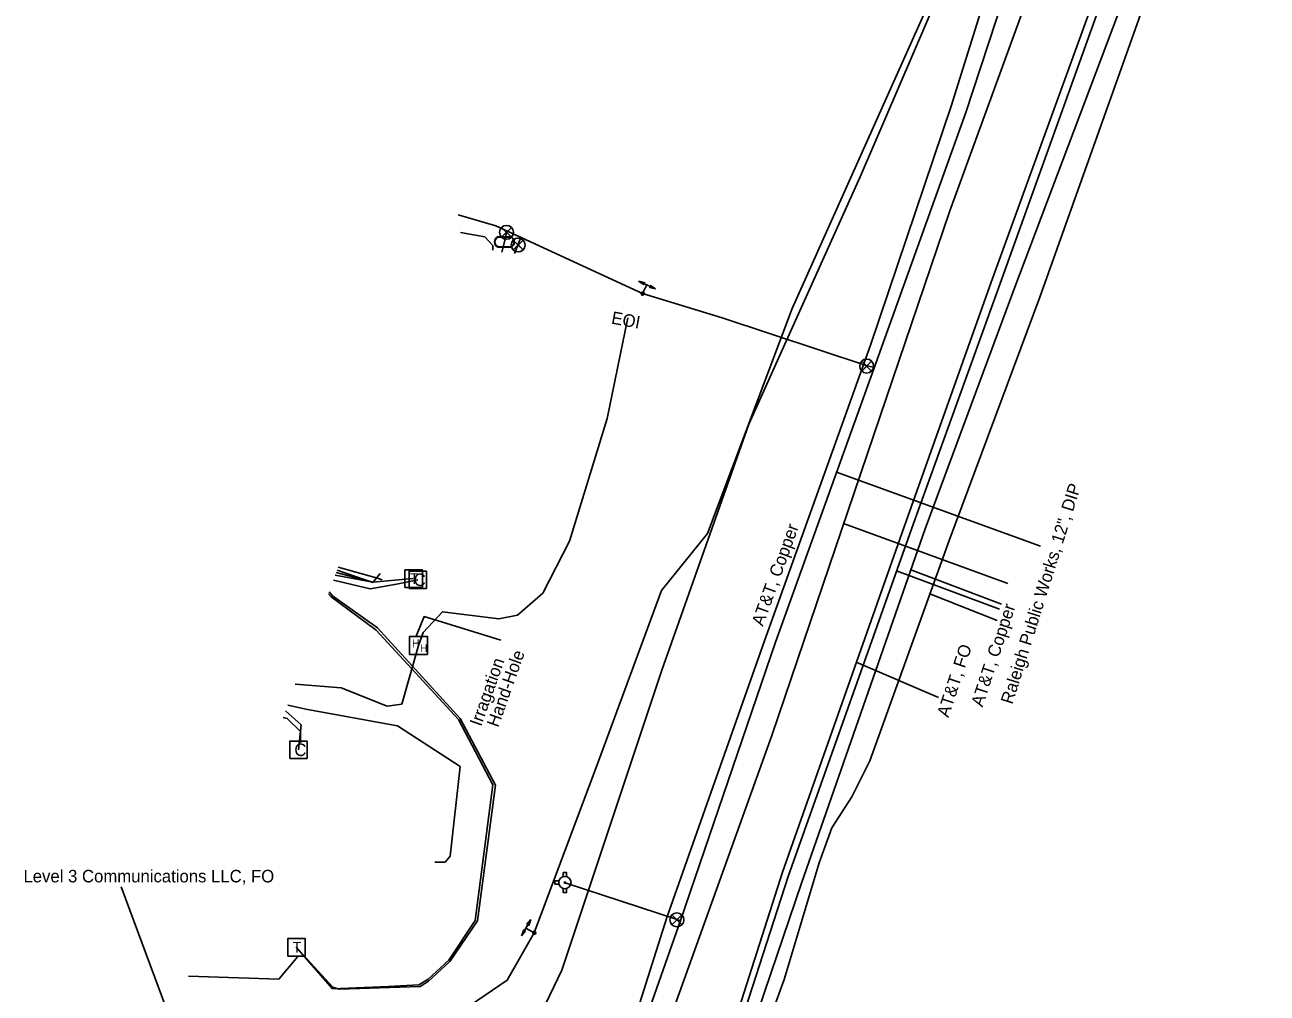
# Model space of a CAD drawing. Extents: x 2070721 to 2083340, y 729290 to 737883.
# Drawn here: x 2080815 to 2081212.7, y 732995.1 to 733305.1 of the extents above; entities that cross this region are included whole.
import ezdxf

# ---------------------------------------------------------------- set-up
doc = ezdxf.new("R2010")
doc.units = 0
for name, color, linetype in [('Exist Utilities Gas UG Line SUE LOS B', 7, 'Continuous'), ('Exist Utilities Power Hand Hole CELL', 7, 'Continuous'), ('Exist Utilities Power Hand Hole Leader', 7, 'Continuous'), ('Exist Utilities Power Hand Hole Text', 7, 'Continuous'), ('Exist Utilities Power UG Cable SUE LOS B', 7, 'Continuous'), ('Exist Utilities Telephone Change of Service SUE CELL', 7, 'Continuous'), ('Exist Utilities Telephone Pedestal CELL', 7, 'Continuous'), ('Exist Utilities Telephone UG Cable SUE LOS C', 7, 'Continuous'), ('Exist Utilities Telephone UG Cable SUE LOS C Leader', 7, 'Continuous'), ('Exist Utilities Telephone UG Cable SUE LOS C Text', 7, 'Continuous'), ('Exist Utilities Telephone UG FO SUE LOS B', 7, 'Continuous'), ('Exist Utilities Telephone UG FO SUE LOS B Leader', 7, 'Continuous'), ('Exist Utilities Telephone UG FO SUE LOS B Text', 7, 'Continuous'), ('Exist Utilities Telephone UG FO SUE LOS C', 7, 'Continuous'), ('Exist Utilities Telephone UG FO SUE LOS C Leader', 7, 'Continuous'), ('Exist Utilities Telephone UG FO SUE LOS C Text', 7, 'Continuous'), ('Exist Utilities TV Pedestal CELL', 7, 'Continuous'), ('Exist Utilities TV UG Cable SUE LOS C', 7, 'Continuous'), ('Exist Utilities Water Change of Service SUE CELL', 7, 'Continuous'), ('Exist Utilities Water Fire Hydrant CELL', 7, 'Continuous'), ('Exist Utilities Water Meter CELL', 7, 'Continuous'), ('Exist Utilities Water UG Line SUE LOS B', 7, 'Continuous'), ('Exist Utilities Water UG Line SUE LOS B Leader', 7, 'Continuous'), ('Exist Utilities Water UG Line SUE LOS B Text', 7, 'Continuous'), ('Exist Utilities Water UG Line SUE LOS C', 7, 'Continuous'), ('Exist Utilities Water Valve CELL', 7, 'Continuous')]:
    doc.layers.add(name, color=color, linetype=linetype)

msp = doc.modelspace()

# ---------------------------------------------------------------- linework, layer by layer
at = {"layer": 'Exist Utilities Gas UG Line SUE LOS B'}
msp.add_lwpolyline([(2080924.17, 732884.04), (2080930.33, 732882.17), (2080949.02, 732923.62), (2080986.84, 733002.49), (2081018.88, 733098.52), (2081046.79, 733177.28), (2081082.41, 733256.43), (2081124.09, 733353.56), (2081157.6, 733423.49)], dxfattribs=at)
at = {"layer": 'Exist Utilities Power Hand Hole CELL'}
msp.add_line((2080941.08, 733106.31), (2080941.08, 733106.31), dxfattribs=at)
msp.add_lwpolyline([(2080938.13, 733103.58), (2080943.88, 733103.58), (2080943.88, 733109.33), (2080938.13, 733109.33), (2080938.13, 733103.58)], dxfattribs=at)
at = {"layer": 'Exist Utilities Power Hand Hole Leader'}
msp.add_lwpolyline([(2080940.24, 733109.35), (2080942.86, 733115.65), (2080967.41, 733108.17)], dxfattribs=at)
at = {"layer": 'Exist Utilities Power UG Cable SUE LOS B'}
for points in [[(2080964.78, 733232.99), (2080964.78, 733234.42), (2080962.25, 733237.2), (2080954.44, 733238.62)], [(2080935.69, 733087.68), (2080940.98, 733106.38), (2080942.52, 733110.53), (2080948.63, 733117.2), (2080966.72, 733114.92), (2080972.71, 733116.12), (2080980.82, 733123.17), (2080989.3, 733139.79), (2081001.41, 733179.09), (2081008, 733211.34)], [(2080929.38, 733127.43), (2080927.91, 733127.95), (2080915.26, 733131.44)], [(2080914.92, 733130.51), (2080926.37, 733126.62), (2080928.73, 733129.47)], [(2080935.69, 733087.68), (2080930.93, 733087), (2080916.25, 733092.82), (2080901.57, 733094)], [(2080899.12, 733087.29), (2080905.51, 733085.89), (2080934.27, 733080.68), (2080954.39, 733067.67), (2080951.13, 733038.98), (2080949.52, 733037.11), (2080946.26, 733037.11)], [(2080897.68, 733083.35), (2080898.97, 733083.08), (2080903.24, 733078.92), (2080903.24, 733075.29)], [(2080867.39, 733000.52), (2080896.29, 732999.64), (2080902.38, 733006.86)]]:
    msp.add_lwpolyline(points, dxfattribs=at)
at = {"layer": 'Exist Utilities Telephone Change of Service SUE CELL'}
for p, q in [((2080976.94, 733018.69), (2080973.99, 733013.51)), ((2080975.39, 733015.97), (2080976.94, 733018.69)), ((2080978.07, 733014.44), (2080975.39, 733015.97)), ((2080978.07, 733014.44), (2080978.07, 733014.44))]:
    msp.add_line(p, q, dxfattribs=at)
for points in [[(2080976.94, 733018.69), (2080976.27, 733016.81), (2080976.18, 733017.35), (2080975.72, 733017.17)], [(2080973.99, 733013.51), (2080974.67, 733015.4), (2080974.76, 733014.86), (2080975.21, 733015.04)]]:
    msp.add_lwpolyline(points, close=True, dxfattribs=at)
msp.add_circle((2080978.07, 733014.44), 0.517, dxfattribs=at)
at = {"layer": 'Exist Utilities Telephone Pedestal CELL'}
for p, q in [((2080939.36, 733127.86), (2080939.36, 733127.86)), ((2080901.87, 733009.84), (2080901.87, 733009.84))]:
    msp.add_line(p, q, dxfattribs=at)
for points in [[(2080936.63, 733125.03), (2080942.23, 733125.03), (2080942.23, 733130.63), (2080936.63, 733130.63), (2080936.63, 733125.03)], [(2080899.15, 733007.01), (2080904.74, 733007.01), (2080904.74, 733012.61), (2080899.15, 733012.61), (2080899.15, 733007.01)]]:
    msp.add_lwpolyline(points, dxfattribs=at)
at = {"layer": 'Exist Utilities Telephone UG Cable SUE LOS C'}
for points in [[(2080953.21, 732796.69), (2081054.09, 733077.62), (2081111.09, 733245.57), (2081176.08, 733423.78), (2081231.97, 733580.28), (2081320.16, 733847.08), (2081418.84, 734093.09), (2081467.34, 734224.03), (2081494.06, 734287.2), (2081526.74, 734352.01), (2081556, 734404.62), (2081808.13, 734757.73), (2081845.73, 734804.26), (2081874.67, 734821.58), (2081898.66, 734810.94), (2081917.15, 734795.51)], [(2080971.45, 732791.05), (2081028.93, 732955.93), (2081037.58, 732965.12), (2081059.34, 733032.5), (2081099.5, 733145.5), (2081127.24, 733222.27), (2081165.53, 733329.08), (2081197.08, 733415.76), (2081225.51, 733493.81), (2081252.34, 733568.18), (2081252.65, 733568.73)], [(2080977.85, 732787.5), (2081009.55, 732879.6), (2081045.87, 732978.13), (2081063.56, 733030.35), (2081103.18, 733143.81), (2081131.57, 733220.23), (2081172.06, 733327.38), (2081203.1, 733413.05), (2081232.13, 733491.49), (2081257.07, 733565.11), (2081257.51, 733566.68)], [(2080980.31, 732787.04), (2081017.13, 732880.26), (2081044.65, 732962.53), (2081058.02, 732999.54), (2081069.26, 733036.84), (2081073.31, 733048.09), (2081079.75, 733057.99), (2081085.51, 733069.49), (2081110.84, 733140.06), (2081139.9, 733217.95), (2081177.19, 733322.59), (2081208.97, 733410.75), (2081237.5, 733489.4), (2081264.77, 733561.01)], [(2080944.31, 732798.44), (2080951.65, 732814.71), (2080971.81, 732874.01), (2081001.7, 732960.05), (2081020.52, 733019.4), (2081051.78, 733107.87), (2081085.75, 733202.6), (2081111.57, 733279.04), (2081128.94, 733334.77), (2081148.26, 733379.04), (2081175.1, 733448.52), (2081180.53, 733478.86)], [(2080939.29, 733127.87), (2080926.33, 733126.73), (2080914.34, 733128.93)], [(2080944.24, 732998.92), (2080950.99, 733005.26), (2080959.87, 733018.3), (2080965.67, 733061.66), (2080954.33, 733083.1), (2080927.85, 733112.11), (2080913.43, 733122.3), (2080912.38, 733123.56)], [(2080944.24, 732998.92), (2080941.57, 732997.28), (2080915.55, 732996.45), (2080913.58, 732997), (2080901.87, 733009.83)]]:
    msp.add_lwpolyline(points, dxfattribs=at)
at = {"layer": 'Exist Utilities Telephone UG Cable SUE LOS C Leader'}
for p, q in [((2081077.1, 733145.5), (2081129.64, 733126.3)), ((2081094.04, 733130.35), (2081127.01, 733118.02)), ((2081098.66, 733130.6), (2081127.65, 733119.69)), ((2081104.65, 733122.9), (2081126.24, 733114.42))]:
    msp.add_line(p, q, dxfattribs=at)
at = {"layer": 'Exist Utilities Telephone UG FO SUE LOS B'}
for points in [[(2081060.57, 733214.24), (2081129.62, 733368.62), (2081142.99, 733409.6), (2081173.13, 733492.79), (2081185.02, 733525.68), (2081211.4, 733608.97), (2081237.57, 733665.91), (2081235.81, 733672.2)], [(2080974.54, 732788.58), (2081004.48, 732877.32), (2081038.77, 732975.1), (2081057.5, 733033.86), (2081097.09, 733146.25), (2081124.3, 733222.73), (2081163.35, 733330.31), (2081194.31, 733416.96), (2081222.79, 733494.92), (2081247.13, 733564.12), (2081248.81, 733567.64)], [(2080978.07, 733014.44), (2080998.67, 733069.39), (2081018.84, 733124), (2081033.47, 733142.22), (2081060.57, 733214.24)], [(2080939.29, 733127.87), (2080926.33, 733126.73), (2080914.65, 733129.77)], [(2080944.08, 732999.62), (2080950.66, 733005.65), (2080959.18, 733018.4), (2080964.82, 733061.81), (2080953.78, 733082.77), (2080927.47, 733111.31), (2080913.03, 733121.96), (2080912.17, 733123)], [(2080944.08, 732999.62), (2080941.08, 732997.75), (2080931.36, 732997.26), (2080913.5, 732996.51), (2080901.87, 733009.84)]]:
    msp.add_lwpolyline(points, dxfattribs=at)
at = {"layer": 'Exist Utilities Telephone UG FO SUE LOS B Leader'}
msp.add_line((2081081.16, 733101.05), (2081107.43, 733089.72), dxfattribs=at)
at = {"layer": 'Exist Utilities Telephone UG FO SUE LOS C'}
msp.add_lwpolyline([(2080858.37, 732979.69), (2080864.15, 732979.69), (2080906.18, 732979.56), (2080947.92, 732984.72), (2080969.41, 732999.27), (2080978.07, 733014.44)], dxfattribs=at)
at = {"layer": 'Exist Utilities Telephone UG FO SUE LOS C Leader'}
msp.add_line((2080864.15, 732979.69), (2080845.85, 733029.15), dxfattribs=at)
at = {"layer": 'Exist Utilities TV Pedestal CELL'}
for p, q in [((2080940.76, 733127.44), (2080940.76, 733127.44)), ((2080902.54, 733073.03), (2080902.54, 733073.03))]:
    msp.add_line(p, q, dxfattribs=at)
for points in [[(2080937.99, 733124.67), (2080943.54, 733124.67), (2080943.54, 733130.22), (2080937.99, 733130.22), (2080937.99, 733124.67)], [(2080899.77, 733070.26), (2080905.32, 733070.26), (2080905.32, 733075.81), (2080899.77, 733075.81), (2080899.77, 733070.26)]]:
    msp.add_lwpolyline(points, dxfattribs=at)
at = {"layer": 'Exist Utilities TV UG Cable SUE LOS C'}
for points in [[(2080940.76, 733127.44), (2080933.93, 733126.02), (2080925.57, 733124.53), (2080913.77, 733127.35)], [(2080902.61, 733073), (2080903.41, 733080.99), (2080898.47, 733085.52)]]:
    msp.add_lwpolyline(points, dxfattribs=at)
at = {"layer": 'Exist Utilities Water Change of Service SUE CELL'}
for p, q in [((2081016.89, 733220.53), (2081011.48, 733223.04)), ((2081012.75, 733219.05), (2081014.05, 733221.85)), ((2081012.75, 733219.05), (2081012.75, 733219.05)), ((2081014.05, 733221.85), (2081016.89, 733220.53))]:
    msp.add_line(p, q, dxfattribs=at)
for points in [[(2081011.48, 733223.04), (2081013.41, 733222.52), (2081012.89, 733222.38), (2081013.11, 733221.95)], [(2081016.89, 733220.53), (2081014.96, 733221.05), (2081015.49, 733221.18), (2081015.27, 733221.62)]]:
    msp.add_lwpolyline(points, close=True, dxfattribs=at)
msp.add_circle((2081012.75, 733219.05), 0.517, dxfattribs=at)
at = {"layer": 'Exist Utilities Water Fire Hydrant CELL'}
msp.add_line((2080987.87, 733030.54), (2080987.87, 733030.54), dxfattribs=at)
for points in [[(2080987.36, 733032.45), (2080987.36, 733033.74), (2080988.38, 733033.74), (2080988.38, 733032.43)], [(2080985.96, 733031.05), (2080984.67, 733031.05), (2080984.67, 733030.03), (2080985.96, 733030.03)], [(2080987.36, 733028.63), (2080987.36, 733027.34), (2080988.38, 733027.34), (2080988.38, 733028.65)]]:
    msp.add_lwpolyline(points, dxfattribs=at)
for radius in [1.98, 0.243]:
    msp.add_circle((2080987.87, 733030.54), radius, dxfattribs=at)
at = {"layer": 'Exist Utilities Water Meter CELL'}
msp.add_line((2080968.52, 733235.58), (2080968.52, 733235.58), dxfattribs=at)
for points in [[(2080966.48, 733237.28), (2080970.56, 733237.28)], [(2080966.48, 733237.15), (2080970.56, 733237.15)], [(2080970.56, 733234.02), (2080966.46, 733234.02)], [(2080970.56, 733233.88), (2080966.46, 733233.88)]]:
    msp.add_lwpolyline(points, dxfattribs=at)
for centre, radius, start, end in [((2080967.21, 733235.58), 1.86, 113.178, 245.9794), ((2080967.22, 733235.58), 1.73, 115.3009, 243.7824), ((2080969.81, 733235.59), 1.86, 293.6483, 66.3084), ((2080969.82, 733235.58), 1.73, 295.1272, 64.8728)]:
    msp.add_arc(centre, radius, start, end, dxfattribs=at)
at = {"layer": 'Exist Utilities Water UG Line SUE LOS B'}
for points in [[(2080968.02, 732853.09), (2080971.09, 732863.55), (2080973.36, 732870.49), (2081004.03, 732959.14), (2081024.87, 733018.36), (2081055.27, 733107.45), (2081086.77, 733195.01), (2081116.19, 733277.07), (2081135.71, 733336.57)], [(2081012.75, 733219.05), (2081038.17, 733211.25), (2081084.66, 733195.95), (2081086.52, 733195.46)], [(2081024.85, 733018.29), (2081023.77, 733018.7), (2080987.96, 733030.47)]]:
    msp.add_lwpolyline(points, dxfattribs=at)
at = {"layer": 'Exist Utilities Water UG Line SUE LOS B Leader'}
msp.add_line((2081074.84, 733161.91), (2081140.08, 733138.21), dxfattribs=at)
at = {"layer": 'Exist Utilities Water UG Line SUE LOS C'}
for p, q in [((2080969.33, 733239.15), (2080968.52, 733235.58)), ((2080968.52, 733235.58), (2080967.64, 733232.28)), ((2080973.8, 733237.05), (2080971.75, 733231.84))]:
    msp.add_line(p, q, dxfattribs=at)
msp.add_lwpolyline([(2081012.75, 733219.05), (2080965.74, 733240.78), (2080953.65, 733244.3)], dxfattribs=at)
at = {"layer": 'Exist Utilities Water Valve CELL'}
for points in [[(2080970.76, 733240.24), (2080967.61, 733237.09), (2080969.18, 733238.67), (2080970.76, 733237.09), (2080967.61, 733240.24)], [(2080974.46, 733236.18), (2080971.31, 733233.03), (2080972.89, 733234.61), (2080974.46, 733233.03), (2080971.31, 733236.18)], [(2081086.05, 733197.43), (2081082.9, 733194.28), (2081084.47, 733195.86), (2081086.05, 733194.28), (2081082.9, 733197.43)], [(2081025.3, 733020.19), (2081022.15, 733017.04), (2081023.73, 733018.62), (2081025.3, 733017.04), (2081022.15, 733020.19)]]:
    msp.add_lwpolyline(points, dxfattribs=at)
for centre in [(2080969.18, 733238.67), (2080972.89, 733234.61), (2081084.47, 733195.86), (2081023.73, 733018.62)]:
    msp.add_circle(centre, 2.23, dxfattribs=at)

# ---------------------------------------------------------------- texts
at = {"layer": 'Exist Utilities Power Hand Hole CELL'}
for p in [(2080938.92, 733105.84), (2080941.48, 733104.31)]:
    msp.add_text('H', height=2.5, dxfattribs=at).set_placement(p)
at = {"layer": 'Exist Utilities Power Hand Hole Text'}
for s, rotation, p in [('EOI', 349.5989, (2081002.52, 733209.48)), ('Hand-Hole', 70.368, (2080966.5, 733079.99)), ('Irragation ', 70.368, (2080961.03, 733080.3))]:
    msp.add_text(s, height=4, rotation=rotation, dxfattribs=at).set_placement(p)
at = {"layer": 'Exist Utilities Telephone Pedestal CELL'}
for p in [(2080938.23, 733126.14), (2080900.74, 733008.13)]:
    msp.add_text('T', height=3.42, dxfattribs=at).set_placement(p)
at = {"layer": 'Exist Utilities Telephone UG Cable SUE LOS C Text'}
for rotation, p in [(70.2708, (2081051.26, 733112.34)), (71.9145, (2081121.57, 733086.51))]:
    msp.add_text('AT&T, Copper', height=4, rotation=rotation, dxfattribs=at).set_placement(p)
at = {"layer": 'Exist Utilities Telephone UG FO SUE LOS B Text'}
msp.add_text('AT&T, FO', height=4, rotation=71.7158, dxfattribs=at).set_placement((2081110.66, 733083.14))
at = {"layer": 'Exist Utilities Telephone UG FO SUE LOS C Text'}
msp.add_text('Level 3 Communications LLC, FO', height=4, dxfattribs=at).set_placement((2080814.54, 733030.59))
at = {"layer": 'Exist Utilities TV Pedestal CELL'}
for p in [(2080939.46, 733125.44), (2080901.24, 733071.03)]:
    msp.add_text('C', height=4, dxfattribs=at).set_placement(p)
at = {"layer": 'Exist Utilities Water UG Line SUE LOS B Text'}
msp.add_text('Raleigh Public Works, 12", DIP ', height=4, rotation=72.5496, dxfattribs=at).set_placement((2081131.1, 733087.38))

doc.saveas('drawing.dxf')
